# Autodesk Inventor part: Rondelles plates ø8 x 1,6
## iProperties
Created: 2002-05
Part Number: Rondelles plates ø8 x 1,6
Material: Par défaut
Catalog Web Link: www.traceparts.com
Description: Rondelles plates: M8
Document SubType Name: Modélisation
Standard: BS 4320
Designer: REVEST Pierre
Control State: 0
Master: False
Checked Out: False
Shininess: 20.0
Length Units: 11269
Angle Units: 11279
Time Units: 11290
Mass Units: 11283
Length Display Precision: 3
Angle Display Precision: 2
Density: 0.0
Volumn: 0.0
Area: 0.0
PropertySet Name: Model Information
Author: REVEST Pierre
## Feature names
1. Base1
